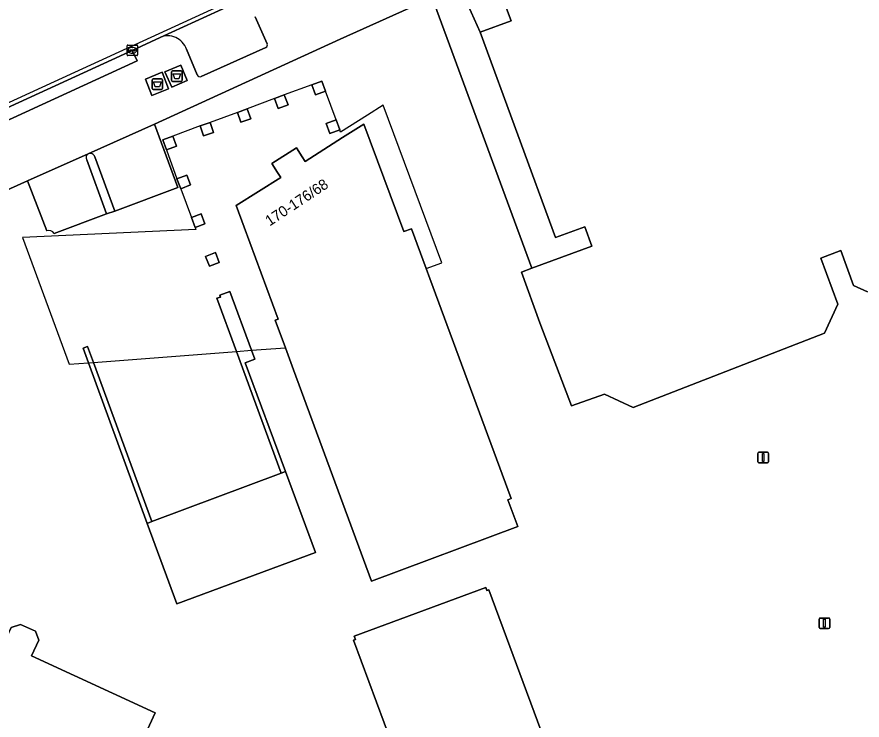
# Model space of a CAD drawing. Extents: x 160806 to 161707, y 383696 to 384148.
# Drawn here: x 161003.1 to 161082.8, y 383930 to 383996.3 of the extents above; entities that cross this region are included whole.
import ezdxf

# ---------------------------------------------------------------- set-up
doc = ezdxf.new("R2010")
doc.units = 0
for name, color, linetype in [('IMGEO_Afval_apart_plaats', 7, 'Continuous'), ('IMGEO_Kolk', 7, 'Continuous'), ('IMGEO_Lichtmast', 7, 'Continuous'), ('IMGEO_Muur', 7, 'Continuous'), ('IMGEO_Pand', 7, 'Continuous'), ('IMGEO_Pand_nummerreeks', 7, 'Continuous'), ('IMGEO_Pand_overbouw', 7, 'Continuous'), ('IMGEO_Parkeervlak_open', 7, 'Continuous'), ('IMGEO_Rijbaan_lokaal_open', 7, 'Continuous'), ('IMGEO_Terreindeel_gesloten', 7, 'Continuous'), ('IMGEO_Verkeerseiland_open', 7, 'Continuous'), ('IMGEO_Voetpad_gesloten', 7, 'Continuous'), ('IMGEO_Voetpad_open', 7, 'Continuous')]:
    doc.layers.add(name, color=color, linetype=linetype)

msp = doc.modelspace()

# ---------------------------------------------------------------- linework, layer by layer
at = {"layer": 'IMGEO_Afval_apart_plaats'}
for p, q in [((161017.752, 383991.248), (161018.542, 383991.248)), ((161018.542, 383991.248), (161017.752, 383991.248)), ((161015.914, 383990.48), (161016.704, 383990.48)), ((161016.704, 383990.48), (161015.914, 383990.48)), ((161017.652, 383990.348), (161017.652, 383991.148)), ((161017.652, 383991.148), (161017.652, 383990.348)), ((161018.642, 383991.148), (161018.642, 383990.348)), ((161018.642, 383990.348), (161018.642, 383991.148)), ((161015.814, 383989.58), (161015.814, 383990.38)), ((161015.814, 383990.38), (161015.814, 383989.58)), ((161016.804, 383990.38), (161016.804, 383989.58)), ((161016.804, 383989.58), (161016.804, 383990.38)), ((161018.542, 383990.248), (161017.752, 383990.248)), ((161017.752, 383990.248), (161018.542, 383990.248)), ((161016.704, 383989.48), (161015.914, 383989.48)), ((161015.914, 383989.48), (161016.704, 383989.48))]:
    msp.add_line(p, q, dxfattribs=at)
for points in [[(161017.795, 383990.962), (161018.499, 383990.962), (161018.35, 383990.492), (161017.944, 383990.492), (161017.795, 383990.962)], [(161015.957, 383990.194), (161016.661, 383990.194), (161016.512, 383989.724), (161016.106, 383989.724), (161015.957, 383990.194)]]:
    msp.add_lwpolyline(points, dxfattribs=at)
for centre, start, end in [((161017.752, 383991.148), 90, 180), ((161017.752, 383991.148), 90, 180), ((161018.542, 383991.148), 0, 90), ((161018.542, 383991.148), 360, 90), ((161015.914, 383990.38), 90, 180), ((161015.914, 383990.38), 90, 180), ((161016.704, 383990.38), 0, 90), ((161016.704, 383990.38), 360, 90), ((161017.752, 383990.348), 180, 270), ((161017.752, 383990.348), 180, 270), ((161018.542, 383990.348), 270, 0), ((161018.542, 383990.348), 270, 0), ((161015.914, 383989.58), 180, 270), ((161015.914, 383989.58), 180, 270), ((161016.704, 383989.58), 270, 0), ((161016.704, 383989.58), 270, 0)]:
    msp.add_arc(centre, 0.1, start, end, dxfattribs=at)
at = {"layer": 'IMGEO_Kolk'}
for p, q in [((161013.446, 383992.748), (161013.446, 383993.6)), ((161013.521, 383993.674), (161014.373, 383993.674)), ((161014.447, 383993.6), (161014.447, 383992.748)), ((161013.705, 383993.168), (161013.705, 383993.18)), ((161014.143, 383993.131), (161013.745, 383993.131)), ((161013.748, 383993.217), (161014.146, 383993.217)), ((161013.957, 383992.894), (161013.932, 383992.894)), ((161013.934, 383993.454), (161013.959, 383993.454)), ((161014.189, 383993.18), (161014.189, 383993.168)), ((161014.373, 383992.674), (161013.521, 383992.674))]:
    msp.add_line(p, q, dxfattribs=at)
for points in [[(161013.446, 383992.748), (161013.446, 383993.6)], [(161013.521, 383993.674), (161014.373, 383993.674)], [(161014.447, 383993.6), (161014.447, 383992.748)], [(161014.373, 383992.674), (161013.521, 383992.674)]]:
    msp.add_lwpolyline(points, dxfattribs=at)
for centre, radius, start, end in [((161013.523, 383993.598), 0.0765, 91.55205, 178.44795), ((161013.523, 383993.598), 0.0765, 91.55205, 178.44795), ((161014.371, 383993.598), 0.0765, 1.55205, 88.44795), ((161014.371, 383993.598), 0.0765, 1.55205, 88.44795), ((161013.745, 383993.177), 0.0403, 85.87752, 175.75265), ((161013.742, 383993.167), 0.0366, 178.93798, 274.71019), ((161014.146, 383993.174), 0.043, 264.86636, 352.45326), ((161014.15, 383993.179), 0.0386, 1.73085, 96.63898), ((161013.523, 383992.75), 0.0765, 181.55205, 268.44795), ((161013.523, 383992.75), 0.0765, 181.55205, 268.44795), ((161014.371, 383992.75), 0.0765, 271.55205, 358.44795), ((161014.371, 383992.75), 0.0765, 271.55205, 358.44795)]:
    msp.add_arc(centre, radius, start, end, dxfattribs=at)
for centre, major_axis, ratio, start_param, end_param in [((161013.933, 383993.174), (-0.387, 0.002), 0.722429, 4.712389, 7.853982), ((161013.958, 383993.174), (-0.39, 0.002), 0.717154, 1.570796, 4.712389)]:
    msp.add_ellipse(centre, major_axis=major_axis, ratio=ratio, start_param=start_param, end_param=end_param, dxfattribs=at)
at = {"layer": 'IMGEO_Lichtmast'}
for p, q in [((161072.983, 383954.366), (161072.983, 383955.166)), ((161072.983, 383955.166), (161072.983, 383954.366)), ((161073.083, 383955.266), (161073.873, 383955.266)), ((161073.873, 383955.266), (161073.083, 383955.266)), ((161073.973, 383955.166), (161073.973, 383954.366)), ((161073.973, 383954.366), (161073.973, 383955.166)), ((161073.873, 383954.266), (161073.083, 383954.266)), ((161073.083, 383954.266), (161073.873, 383954.266)), ((161078.763, 383938.742), (161078.763, 383939.542)), ((161078.763, 383939.542), (161078.763, 383938.742)), ((161078.863, 383939.642), (161079.653, 383939.642)), ((161079.653, 383939.642), (161078.863, 383939.642)), ((161079.753, 383939.542), (161079.753, 383938.742)), ((161079.753, 383938.742), (161079.753, 383939.542)), ((161079.653, 383938.642), (161078.863, 383938.642)), ((161078.863, 383938.642), (161079.653, 383938.642))]:
    msp.add_line(p, q, dxfattribs=at)
for points in [[(161073.403, 383955.141), (161073.553, 383955.141), (161073.553, 383954.391), (161073.403, 383954.391), (161073.403, 383955.141)], [(161079.183, 383939.517), (161079.333, 383939.517), (161079.333, 383938.767), (161079.183, 383938.767), (161079.183, 383939.517)]]:
    msp.add_lwpolyline(points, dxfattribs=at)
for centre, start, end in [((161073.083, 383955.166), 90, 180), ((161073.083, 383955.166), 90, 180), ((161073.873, 383955.166), 0, 90), ((161073.873, 383955.166), 360, 90), ((161073.083, 383954.366), 180, 270), ((161073.083, 383954.366), 180, 270), ((161073.873, 383954.366), 270, 0), ((161073.873, 383954.366), 270, 0), ((161078.863, 383939.542), 90, 180), ((161078.863, 383939.542), 90, 180), ((161079.653, 383939.542), 0, 90), ((161079.653, 383939.542), 360, 90), ((161078.863, 383938.742), 180, 270), ((161078.863, 383938.742), 180, 270), ((161079.653, 383938.742), 270, 0), ((161079.653, 383938.742), 270, 0)]:
    msp.add_arc(centre, 0.1, start, end, dxfattribs=at)
at = {"layer": 'IMGEO_Muur'}
for points in [[(161023.769, 383964.777), (161028.006, 383953.311), (161028.394, 383953.457), (161024.585, 383963.712), (161025.517, 383964.059), (161025.209, 383964.887), (161023.149, 383970.43), (161022.217, 383970.084), (161022.283, 383969.906), (161021.913, 383969.799)], [(161010.275, 383963.748), (161009.724, 383965.245), (161009.295, 383965.084), (161009.799, 383963.711), (161015.359, 383948.563), (161015.805, 383948.731)]]:
    msp.add_lwpolyline(points, close=True, dxfattribs=at)
at = {"layer": 'IMGEO_Pand'}
for points in [[(161085.223, 384011.506), (161076.291, 384008.231), (161075.766, 384009.535), (161048.417, 383999.403), (161049.694, 383995.956), (161046.766, 383994.877), (161053.896, 383975.534), (161056.634, 383976.543), (161057.312, 383974.704), (161051.661, 383972.634), (161050.66, 383972.267), (161052.414, 383967.479), (161055.383, 383959.639), (161058.517, 383960.756), (161061.198, 383959.507), (161079.25, 383966.494), (161080.52, 383969.246), (161078.917, 383973.592), (161080.801, 383974.286), (161082.015, 383971.009), (161083.322, 383970.394)], [(161006.3, 383909.334), (161016.1, 383930.706), (161004.448, 383936.067), (161005.121, 383937.543), (161004.802, 383938.387), (161003.399, 383939.03), (161002.526, 383938.756), (161001.835, 383937.27), (161000, 383938.112), (160990.19, 383942.611), (160980.975, 383922.577)], [(161055.094, 383922.025), (161047.599, 383942.307), (161047.408, 383942.236), (161047.3, 383942.527), (161034.889, 383937.94), (161035.008, 383937.618), (161034.831, 383937.553), (161040.599, 383921.947)]]:
    msp.add_lwpolyline(points, dxfattribs=at)
for points in [[(161031.232, 383988.991), (161032.167, 383989.335), (161031.826, 383990.262), (161030.891, 383989.918)], [(161027.721, 383987.693), (161028.644, 383988.044), (161028.291, 383988.972), (161027.368, 383988.622)], [(161024.198, 383986.395), (161025.123, 383986.728), (161024.788, 383987.658), (161023.863, 383987.325)], [(161032.248, 383986.269), (161032.588, 383985.337), (161033.515, 383985.675), (161033.175, 383986.607)], [(161020.676, 383985.105), (161021.615, 383985.433), (161021.288, 383986.369), (161020.35, 383986.041)], [(161029.428, 383983.968), (161027.121, 383982.495), (161027.654, 383981.66), (161027.95, 383981.197), (161023.739, 383978.541), (161024.49, 383976.502), (161027.703, 383967.834), (161027.43, 383967.74), (161028.394, 383965.13), (161029.163, 383963.05), (161036.521, 383943.129), (161050.333, 383948.273), (161049.393, 383950.795), (161049.712, 383950.913), (161042.034, 383971.666), (161041.681, 383972.596), (161040.298, 383976.355), (161039.555, 383976.079), (161035.788, 383986.213), (161033.788, 383984.963), (161030.253, 383982.685), (161029.967, 383983.13)], [(161016.831, 383984.729), (161017.167, 383983.795), (161018.108, 383984.135), (161017.772, 383985.068)], [(161019.44, 383980.477), (161019.086, 383981.412), (161018.163, 383981.062), (161018.516, 383980.127)], [(161019.868, 383976.465), (161020.797, 383976.81), (161020.45, 383977.744), (161019.521, 383977.399)], [(161022.146, 383973.169), (161021.786, 383974.099), (161020.86, 383973.741), (161021.22, 383972.811)], [(161015.805, 383948.731), (161015.359, 383948.563), (161018.137, 383940.994), (161031.235, 383945.806), (161028.394, 383953.457), (161028.006, 383953.311)]]:
    msp.add_lwpolyline(points, close=True, dxfattribs=at)
at = {"layer": 'IMGEO_Pand_overbouw'}
msp.add_lwpolyline([(161043.148, 383973.137), (161037.606, 383987.996), (161036.149, 383987.067), (161033.602, 383985.445), (161033.515, 383985.675), (161032.588, 383985.337), (161032.248, 383986.269), (161033.175, 383986.607), (161032.167, 383989.335), (161031.232, 383988.991), (161030.891, 383989.918), (161028.291, 383988.972), (161028.644, 383988.044), (161027.721, 383987.693), (161027.368, 383988.622), (161024.788, 383987.658), (161025.123, 383986.728), (161024.198, 383986.395), (161023.863, 383987.325), (161021.288, 383986.369), (161021.615, 383985.433), (161020.676, 383985.105), (161020.35, 383986.041), (161017.772, 383985.068), (161018.108, 383984.135), (161017.167, 383983.795), (161018.163, 383981.062), (161019.086, 383981.412), (161019.44, 383980.477), (161018.516, 383980.127), (161019.521, 383977.399), (161020.45, 383977.744), (161020.797, 383976.81), (161019.868, 383976.465), (161019.933, 383976.289), (161003.595, 383975.527), (161007.986, 383963.573), (161009.799, 383963.711), (161010.275, 383963.748), (161023.769, 383964.777), (161025.209, 383964.887), (161028.394, 383965.13), (161027.43, 383967.74), (161027.703, 383967.834), (161024.49, 383976.502), (161023.739, 383978.541), (161027.95, 383981.197), (161027.654, 383981.66), (161027.121, 383982.495), (161029.428, 383983.968), (161029.967, 383983.13), (161030.253, 383982.685), (161033.788, 383984.963), (161035.788, 383986.213), (161039.555, 383976.079), (161040.298, 383976.355), (161041.681, 383972.596)], close=True, dxfattribs=at)
at = {"layer": 'IMGEO_Parkeervlak_open'}
for points in [[(161026.469, 383998.931), (161016.563, 383994.396)], [(161026.665, 383993.775), (161025.542, 383996.328)], [(161019.055, 383993.28), (161020.078, 383990.854)], [(161020.453, 383990.696), (161026.55, 383993.448)]]:
    msp.add_lwpolyline(points, dxfattribs=at)
for centre, radius, start, end in [((161017.287, 383992.673), 1.869, 18.94365, 112.80752), ((161026.443, 383993.669), 0.246, 295.80282, 25.44548), ((161020.34, 383990.951), 0.279, 200.35536, 293.95001)]:
    msp.add_arc(centre, radius, start, end, dxfattribs=at)
at = {"layer": 'IMGEO_Rijbaan_lokaal_open'}
msp.add_lwpolyline([(160948.108, 383963.03), (160966.644, 383971.527), (160969.039, 383972.624), (160976.884, 383976.185), (160977.145, 383976.309), (160987.081, 383980.87), (160994.436, 383984.241), (161013.947, 383993.174), (161016.563, 383994.396), (161026.469, 383998.931), (161029.244, 384000.203), (161043.571, 384006.745), (161046.44, 384008.045), (161079.27, 384023.126), (161089.159, 384027.656), (161091.686, 384028.817), (161091.48, 384029.287), (161051.698, 384010.93), (161008.487, 383991.097), (160907.425, 383944.713)], dxfattribs=at)
msp.add_lwpolyline([(161042.251, 383998.166), (161051.661, 383972.634), (161057.312, 383974.704), (161056.634, 383976.543), (161053.896, 383975.534), (161046.766, 383994.877), (161044.796, 383999.32)], close=True, dxfattribs=at)
at = {"layer": 'IMGEO_Terreindeel_gesloten'}
for points in [[(161083.322, 383970.394), (161082.015, 383971.009), (161080.801, 383974.286), (161078.917, 383973.592), (161080.52, 383969.246), (161079.25, 383966.494), (161061.198, 383959.507), (161058.517, 383960.756), (161055.383, 383959.639), (161052.414, 383967.479), (161050.66, 383972.267), (161051.661, 383972.634), (161042.251, 383998.166), (161033.55, 383994.222), (161016.05, 383986.21), (161018.24, 383980.237), (161012.287, 383978.018), (161011.521, 383977.773), (161006.566, 383975.908)], [(161005.888, 383976.146), (161004.053, 383980.875), (160997.944, 383978.148), (160998.353, 383977.077), (160999.676, 383973.574), (160999.337, 383973.451), (160995.462, 383972.051), (160997.341, 383967.036), (160998.393, 383964.227), (161000.341, 383959.026), (161000, 383958.902), (160998.749, 383958.448), (160998.389, 383957.671), (160995.097, 383956.462), (160994.304, 383956.829), (160993.927, 383956.015), (160990.551, 383954.776), (160989.798, 383955.124), (160968.457, 383947.286), (160968.633, 383946.807), (160969.36, 383947.074), (160977.173, 383925.8)], [(160980.975, 383922.577), (160990.19, 383942.611), (161000, 383938.112), (161001.835, 383937.27), (161002.526, 383938.756), (161003.399, 383939.03), (161004.802, 383938.387), (161005.121, 383937.543), (161004.448, 383936.067), (161016.1, 383930.706), (161006.3, 383909.334)], [(161034.831, 383937.553), (161035.008, 383937.618), (161034.889, 383937.94), (161047.3, 383942.527), (161047.408, 383942.236), (161047.599, 383942.307), (161055.094, 383922.025)], [(161040.599, 383921.947), (161034.831, 383937.553)]]:
    msp.add_lwpolyline(points, dxfattribs=at)
for points in [[(161030.891, 383989.918), (161031.826, 383990.262), (161032.167, 383989.335), (161031.232, 383988.991)], [(161027.368, 383988.622), (161028.291, 383988.972), (161028.644, 383988.044), (161027.721, 383987.693)], [(161023.863, 383987.325), (161024.788, 383987.658), (161025.123, 383986.728), (161024.198, 383986.395)], [(161032.588, 383985.337), (161032.248, 383986.269), (161033.175, 383986.607), (161033.515, 383985.675)], [(161020.35, 383986.041), (161021.288, 383986.369), (161021.615, 383985.433), (161020.676, 383985.105)], [(161036.521, 383943.129), (161029.163, 383963.05), (161028.394, 383965.13), (161027.43, 383967.74), (161027.703, 383967.834), (161024.49, 383976.502), (161023.739, 383978.541), (161027.95, 383981.197), (161027.654, 383981.66), (161027.121, 383982.495), (161029.428, 383983.968), (161029.967, 383983.13), (161030.253, 383982.685), (161033.788, 383984.963), (161035.788, 383986.213), (161039.555, 383976.079), (161040.298, 383976.355), (161041.681, 383972.596), (161042.034, 383971.666), (161049.712, 383950.913), (161049.393, 383950.795), (161050.333, 383948.273)], [(161017.167, 383983.795), (161016.831, 383984.729), (161017.772, 383985.068), (161018.108, 383984.135)], [(161018.516, 383980.127), (161018.163, 383981.062), (161019.086, 383981.412), (161019.44, 383980.477)], [(161019.868, 383976.465), (161019.521, 383977.399), (161020.45, 383977.744), (161020.797, 383976.81)], [(161021.22, 383972.811), (161020.86, 383973.741), (161021.786, 383974.099), (161022.146, 383973.169)], [(161018.137, 383940.994), (161015.359, 383948.563), (161009.799, 383963.711), (161009.295, 383965.084), (161009.724, 383965.245), (161010.275, 383963.748), (161015.805, 383948.731), (161028.006, 383953.311), (161023.769, 383964.777), (161021.913, 383969.799), (161022.283, 383969.906), (161022.217, 383970.084), (161023.149, 383970.43), (161025.209, 383964.887), (161025.517, 383964.059), (161024.585, 383963.712), (161028.394, 383953.457), (161031.235, 383945.806)]]:
    msp.add_lwpolyline(points, close=True, dxfattribs=at)
msp.add_arc((161006.093, 383975.646), 0.541, 29.01665, 112.2979, dxfattribs=at)
at = {"layer": 'IMGEO_Verkeerseiland_open'}
msp.add_lwpolyline([(161009.667, 383982.847), (161011.521, 383977.773), (161012.287, 383978.018), (161010.404, 383983.129)], dxfattribs=at)
for centre, radius, start, end in [((161010.005, 383983.078), 0.409, 121.35754, 214.31805), ((161009.954, 383982.982), 0.473, 18.03965, 110.03485)]:
    msp.add_arc(centre, radius, start, end, dxfattribs=at)
at = {"layer": 'IMGEO_Voetpad_gesloten'}
for points in [[(161018.511, 383991.768), (161017.024, 383991.147), (161017.662, 383989.69), (161019.116, 383990.339)], [(161016.749, 383991.111), (161015.184, 383990.472), (161015.79, 383988.906), (161017.358, 383989.531)]]:
    msp.add_lwpolyline(points, close=True, dxfattribs=at)
at = {"layer": 'IMGEO_Voetpad_open'}
for points in [[(161016.05, 383986.21), (161033.55, 383994.222), (161042.251, 383998.166), (161044.796, 383999.32), (161045.113, 383999.3), (161047.022, 384000.146), (161046.899, 384000.438), (161052.328, 384002.909), (161087.151, 384018.873), (161099.091, 384024.316), (161099.383, 384025.462)], [(161025.542, 383996.328), (161026.665, 383993.775)], [(161016.563, 383994.396), (161013.947, 383993.174), (161014.397, 383992.177), (160994.873, 383983.238), (160994.436, 383984.241), (160987.081, 383980.87)], [(161020.078, 383990.854), (161019.055, 383993.28)], [(161026.55, 383993.448), (161020.453, 383990.696)], [(160975.411, 383965.01), (160975.504, 383964.664), (160982.89, 383967.398), (160981.624, 383970.857), (160998.353, 383977.077), (160997.944, 383978.148), (161004.053, 383980.875), (161009.792, 383983.427), (161016.05, 383986.21)], [(161010.404, 383983.129), (161012.287, 383978.018), (161018.24, 383980.237), (161016.05, 383986.21), (161009.792, 383983.427)], [(161009.792, 383983.427), (161004.053, 383980.875), (161005.888, 383976.146)], [(161006.566, 383975.908), (161011.521, 383977.773), (161009.667, 383982.847)]]:
    msp.add_lwpolyline(points, dxfattribs=at)
for points in [[(161096.529, 383985.078), (161095.052, 383984.53), (161095.914, 383982.188), (161098.143, 383982.971), (161087.151, 384018.873), (161052.328, 384002.909), (161046.899, 384000.438), (161047.022, 384000.146), (161045.113, 383999.3), (161044.796, 383999.32), (161046.766, 383994.877), (161049.694, 383995.956), (161048.417, 383999.403), (161075.766, 384009.535), (161076.291, 384008.231), (161085.223, 384011.506), (161085.268, 384011.384), (161090.795, 383996.359), (161092.359, 383992.107), (161092.264, 383992.069), (161092.972, 383990.116), (161094.462, 383990.653)], [(161013.947, 383993.174), (160994.436, 383984.241), (160994.873, 383983.238), (161014.397, 383992.177)], [(161017.024, 383991.147), (161018.511, 383991.768), (161019.116, 383990.339), (161017.662, 383989.69)], [(161015.184, 383990.472), (161016.749, 383991.111), (161017.358, 383989.531), (161015.79, 383988.906)]]:
    msp.add_lwpolyline(points, close=True, dxfattribs=at)
for centre, radius, start, end in [((161017.287, 383992.673), 1.869, 18.94365, 112.80752), ((161026.443, 383993.669), 0.246, 295.80282, 25.44548), ((161020.34, 383990.951), 0.279, 200.35536, 293.95001), ((161010.005, 383983.078), 0.409, 121.35754, 214.31805), ((161009.954, 383982.982), 0.473, 18.03965, 110.03485), ((161006.093, 383975.646), 0.541, 29.01665, 112.2979)]:
    msp.add_arc(centre, radius, start, end, dxfattribs=at)

# ---------------------------------------------------------------- texts
at = {"layer": 'IMGEO_Pand_nummerreeks'}
msp.add_text('170-176/68', height=1, rotation=33.51298, dxfattribs=at).set_placement((161026.906, 383976.559))

doc.saveas('drawing.dxf')
